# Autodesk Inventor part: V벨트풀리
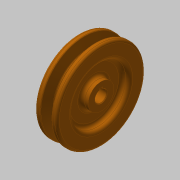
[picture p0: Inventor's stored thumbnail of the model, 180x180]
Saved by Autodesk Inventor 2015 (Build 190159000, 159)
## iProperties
Created: 2015-11
Part Number: V벨트풀리
Material: 알루미늄 6061
Document SubType Name: Modeling
Designer: mduedu
Density: 1 g/cm^3
Appearance: 주황색
Author: mduedu
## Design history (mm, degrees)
sketch "스케치1"
  geometry: L1 (-9.5, 0)-(9.5, 0); L2 (0, 0)-(0, 37.7); L3 (-4.825, 37.7)-(-9.5, 37.7); L4 (-9.5, 37.7)-(-9.5, 0); L5 (0, 28.7)-(-2.074, 28.7); L6 (-2.074, 28.7)-(-4.825, 37.7); L7 (4.825, 37.7)-(9.5, 37.7); L8 (9.5, 37.7)-(9.5, 0); L9 (0, 28.7)-(2.074, 28.7); L10 (2.074, 28.7)-(4.825, 37.7); L11 (-9.5, 35)-(9.5, 35); 3 further points
  constraints: 22 end point, 7 point on line, 4 perpendicular, 3 symmetric about line, 1 coincident, 1 horizontal, 1 horizontal alignment, 1 midpoint, 1 vertical
  dimensions: "d0" = 19 distance of L1.start L1.end; "d2" = 75.4 diameter of L2.end L1 (derived); "d3" = 34 deg angle of L10 L6; "d4" = 6.3 distance between parallel lines of L11 L9; "d5" = 2.7 distance between parallel lines of L7 L11; "d6" = 8 distance of point (4, 35) point (-4, 35); "d7" = 70 diameter of L11 L1
revolve "회전1" sketch "스케치1" stored, may be unused: angle "d8" = 90 deg
sketch "스케치2"
  geometry: C1 r 24 at (0, 0); C2 r 11 at (0, 0); 1 further point
  constraints: 2 centre point, 2 coincident
  dimensions: "d9" = 48 diameter of C1; "d10" = 22 diameter of C2
extrude "돌출1" cut sketch "스케치2" distance "d11" = 6; taper "d12" = 0 deg
fillet "모깎기1" dims "d13" = 3
fillet "모깎기2" dims "d14" = 3
fillet "모깎기3" dims "d15" = 1, "d16" = 0.5, "d17" = 2
hole "구멍1" diameter "d20" = 10; stored, may be unused: countersink angle "d24" = 90 deg, drill point angle "d26" = 118 deg; dims "d18" = 10, "d19" = 10, "d21" = 6, "d22" = 4, "d23" = 2, "d25" = 8
sketch "스케치3"
  geometry: L1 (-1.5, 0)-(1.5, 0); L2 (1.5, 0)-(1.5, 6.4); L3 (1.5, 6.4)-(-1.5, 6.4); L4 (-1.5, 6.4)-(-1.5, 0); 2 further points
  constraints: 8 end point, 2 parallel, 1 coincident, 1 horizontal, 1 midpoint, 1 perpendicular
  dimensions: "d27" = 3 distance of L2.end L3.end; "d29" = 6.4 distance of L3.end L1.start
extrude "돌출2" cut sketch "스케치3" stored distance "d30" = 6; taper "d31" = 0 deg
chamfer "모따기1" distance "d32" = 0.5; stored, may be unused: second distance "d33" = 2, angle "d34" = 45 deg
node "솔리드1"
mirror "대칭1"
